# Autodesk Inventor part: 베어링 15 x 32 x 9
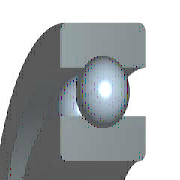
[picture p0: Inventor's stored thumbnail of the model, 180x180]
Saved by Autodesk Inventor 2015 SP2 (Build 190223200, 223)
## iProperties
IsCustomPart: 0
Created: 2012-02
Part Number: 베어링 15 x 32 x 9
Material: 강철, 연강
Description: 깊은 그루브 볼 베어링
Document SubType Name: Modeling
Standard: KS B 2023
Designer: mduedu
Standards Organization: KS
Language: ko-KR
Size Designation: 6002 - 15 x 32 x 9
Categories: <MemberInstance><Categories><Category DisplayName="샤프트 부품" InternalName="7f7aeb1f-a693-4053-b835-cee3144e0d98" Mnemonic="SHFT"><Category DisplayName="베어링" Inter
Density: 1 g/cm^3
Appearance: 강철
Author: mduedu
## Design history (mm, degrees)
sketch "스케치" dims "d0" = 4.42 (= -0.26 x WD + 0.26 x BD)
  geometry: L1 (2.29, 11.75)-(6.71, 11.75); L2 (4.5, 11.75)-(4.5, 9.54); L3 (4.5, 11.75)-(4.5, 13.96); L4 (2.858, 10.271)-(0, 10.271); L5 (0, 7.5)-(9, 7.5); L6 (2.858, 13.229)-(0, 13.229); L7 (0, 16)-(9, 16); L8 (9, 7.5)-(9, 10.271); L9 (6.142, 10.271)-(9, 10.271); L10 (6.142, 13.229)-(9, 13.229); L11 (9, 16)-(9, 13.229); L12 (-1.4, 0)-(8.4, 0) reference; L13 (0, -0.3)-(0, 5.3) reference
  constraints: 22 end point, 4 point on line, 2 collinear, 2 perpendicular, 2 symmetric about line, 1 midpoint, 1 parallel, 14 other
  dimensions: "d9" = 15 diameter of L5 L12 (= WD); "d11" = 32 diameter of L7 L12 (= BD); "d12" = 9 distance between parallel lines of L8 L13 (= KB); "d13" = 20.542 diameter of L9 L12 (= 0.326 x BD + 0.674 x WD)
revolve "본체" stored, may be unused: angle "d6" = 90 deg
revolve "볼" stored, may be unused: angle "d7" = 90 deg
pattern_circular "IDS_ARRAYBALL[SIMPL:T]" dims angle "d3" = 360 deg
body "Solid1"
fillet "모깎기1" dims "d1" = 0.3 (= KRS)
other parameters: "WD" = 15 [user parameter; used in 5 equation terms], "BD" = 32 [user parameter; used in 5 equation terms], "KB" = 9 [user parameter; used in 1 equation term], "KRS" = 0.3 [user parameter; used in 1 equation term], "d4" = 0, "d5" = 0, "d8" = 0, "d14" = 0, "d15" = 0, "BBA" = 0 [user parameter], "BC0" = 2850000 [user parameter], "BC" = 5590000 [user parameter], "BR" = 16 (= 0.5 x BD) [user parameter], "WR" = 7.5 (= 0.5 x WD) [user parameter]
